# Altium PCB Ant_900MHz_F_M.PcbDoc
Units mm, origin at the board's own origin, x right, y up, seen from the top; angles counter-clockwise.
Board outline 23.3 x 33.3 mm, 2 copper layers (Top Layer, Bottom Layer), stack 1.633 mm thick; 3 components, 3 nets, 5 pads, 38 vias.
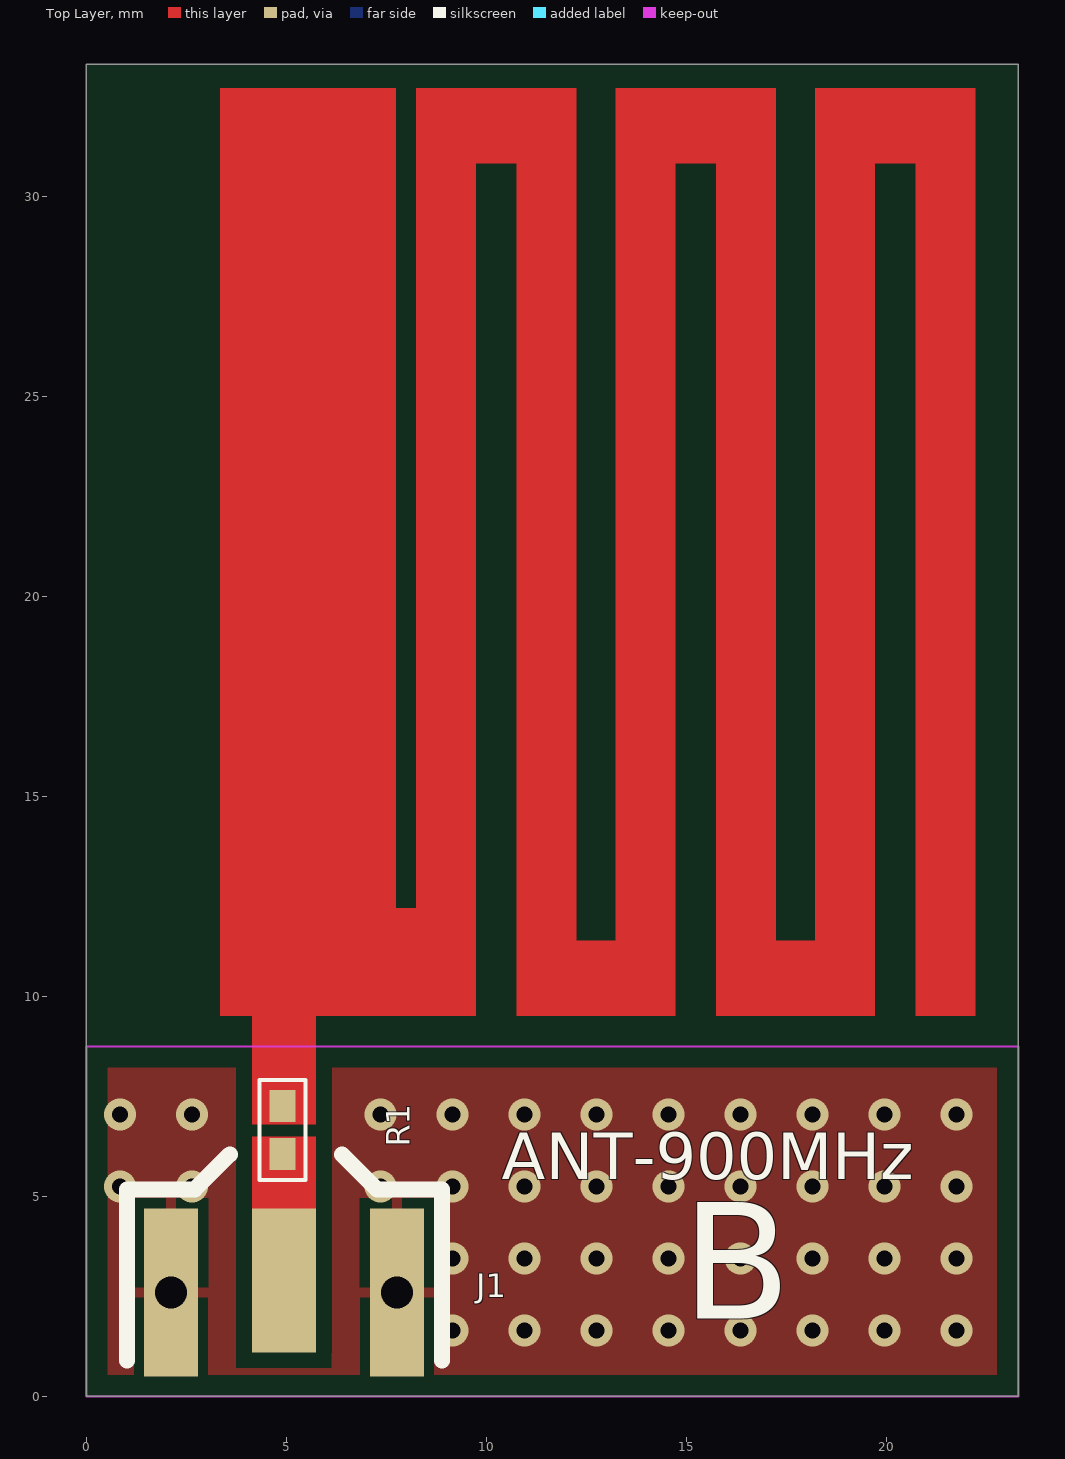
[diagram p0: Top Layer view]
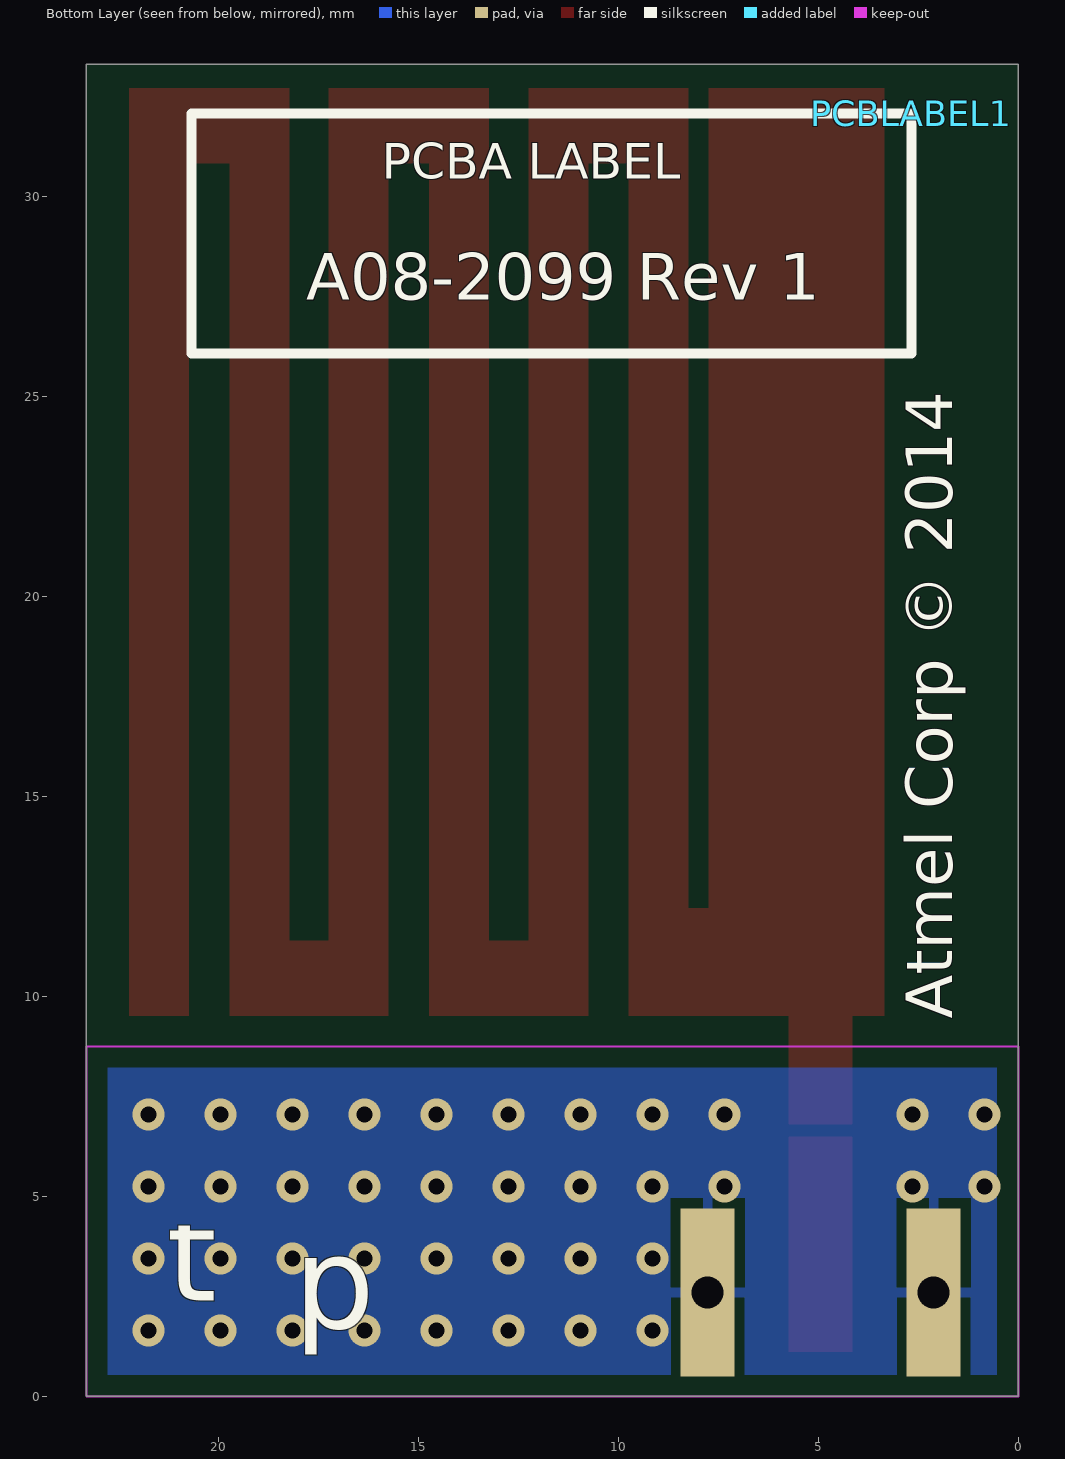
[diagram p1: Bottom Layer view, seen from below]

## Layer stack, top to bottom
Top Solder: solder mask 0.0102, Solder Resist, Dk 3.5
Top Layer: signal copper 0.0356
Dielectric1: core 1.562, FR-4, Dk 4.8
Bottom Layer: signal copper 0.0356
Bottom Solder: solder mask 0.0102, Solder Resist, Dk 3.5

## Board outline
0,0 0,33.3 23.3,33.3 23.3,0

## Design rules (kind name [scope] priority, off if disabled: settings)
AssemblyTestPointUsage [All] p1 off:
AssemblyTestpoint [All] p1 off: testpointundercomponent=TRUE minsize=1.016 maxsize=2.54 preferedsize=1.524 minholesize=0 maxholesize=1.016 preferedholesize=0.813 testpointgrid=0.025 usegrid=TRUE gridtolerance=0 allowsidetop=TRUE allowsidebottom=TRUE
Clearance Clearance_keepout [OnLayer('Keep-Out Layer')] p1: gap=0.5
Clearance Clearance_stripline [All vs (InNet('ANT') or InNet('NetJ1_1'))] p2: gap=0.4
ComponentClearance [All] p1 off: gap=0.254 collisioncheckmode=3 verticalgap=0.254 showdistances=FALSE
DiffPairsRouting [All] p1 off: maxlimit=0.254 minlimit=0.254 mostfreqgap=0.254 toplayer_minwidth=0.381 toplayer_maxwidth=0.381 toplayer_prefwidth=0.381 bottomlayer_minwidth=0.381 bottomlayer_maxwidth=0.381 bottomlayer_prefwidth=0.381 maxuncoupledlength=12.7
FabricationTestPointUsage [All] p1 off: valid=0 allowmultiple=FALSE
FabricationTestpoint [All] p1 off: side=3 testpointundercomponent=TRUE minsize=1.016 maxsize=2.54 preferedsize=1.524 minholesize=0 maxholesize=1.016 preferedholesize=0.813 testpointgrid=0.025 allowsidetop=TRUE allowsidebottom=TRUE usegrid=TRUE gridtolerance=0
FanoutControl Fanout_BGA [IsBGA] p1 off: bgadir=Out bgaviamode=Centered fanoutstyle=Auto fanoutdirection=Alternating viagrid=0.025 // Fanout_BGA (Default Rule)
FanoutControl Fanout_LCC [IsLCC] p2 off: bgadir=Out bgaviamode=Centered fanoutstyle=Auto fanoutdirection=Alternating viagrid=0.025 // Fanout_LCC (Default Rule)
FanoutControl Fanout_SOIC [IsSOIC] p3 off: bgadir=Out bgaviamode=Centered fanoutstyle=Auto fanoutdirection=Alternating viagrid=0.025 // Fanout_SOIC (Default Rule)
FanoutControl Fanout_Small [(CompPinCount < 5)] p4 off: bgadir=Out bgaviamode=Centered fanoutstyle=Auto fanoutdirection=OutThenIn viagrid=0.025 // Fanout_Small (Default Rule)
FanoutControl Fanout_Default [All] p5 off: bgadir=Out bgaviamode=Centered fanoutstyle=Auto fanoutdirection=Alternating viagrid=0.025 // Fanout_Default (Default Rule)
PlaneClearance [All] p1 off: clearance=0.4
PlaneConnect PlaneConnect_via [IsVia] p1 off: planeconnectstyle=Direct reliefexpansion=0.508 reliefentries=4 reliefconductorwidth=0.254 reliefairgap=0.254
PlaneConnect [All] p2 off: planeconnectstyle=Relief reliefexpansion=0.508 reliefentries=4 reliefconductorwidth=0.254 reliefairgap=0.254
PolygonConnect PolygonConnect_via [IsVia] p1: connectstyle=Direct reliefconductorwidth=0.254 reliefentries=4 polygonreliefangle="90 Angle" airgapwidth=0.254
PolygonConnect [All] p2: connectstyle=Relief reliefconductorwidth=0.254 reliefentries=4 polygonreliefangle="90 Angle" airgapwidth=0.254
RoutingVias [All] p1: holewidth=0.4 width=0.8 viastyle="Through Hole" minholewidth=0.3 minwidth=0.6 maxholewidth=0.5 maxwidth=1
SilkToSolderMaskClearance SilkscreenOverComponentPads [IsPad] p1: minsilkscreentomaskgap=0.2 clearancetoexposedcopper=TRUE
SolderMaskExpansion [All] p1: expansion=0.102
Width [All] p1: maxlimit=0.254 minlimit=0.254 preferedwidth=0.254
15 further rules are at their usual default settings.

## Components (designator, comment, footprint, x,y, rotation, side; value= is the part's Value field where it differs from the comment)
J1 "SMA connetor" AP8-00443 4.94,2.9 r90 top locked
PCBLABEL1 "PCBA_LABEL" AP8-00317 2.67,32.07 r0 bottom
R1 "Comment" AP2-00000 4.9,6.66 r90 top

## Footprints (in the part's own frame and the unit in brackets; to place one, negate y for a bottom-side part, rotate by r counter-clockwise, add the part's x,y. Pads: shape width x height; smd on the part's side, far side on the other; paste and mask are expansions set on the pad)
AP2-00000 [mm] "Standard 0402 SMD resistor footprint"
  rect 0.8x0.65 smd: 1(-0.6,0) 2(0.6,0)
  silkscreen extent -1.25,-0.58 1.25,0.58, body extent -0.5,-0.3 0.5,0.3, height 0.2
AP8-00317 [mm] "Placement area for 18x6mm sticker"
  silkscreen extent 0,0 18,6
AP8-00443 [mm] "SMA card edge mount 1.6mm substrate"
  rect 3.6x1.6 smd mask+0: 1(0,0)
  rect 4.2x1.35 hole 0.8 paste-0.3 mask+0: 2(-0.3,-2.825) 2.1(-0.3,2.825)
  silkscreen extent -2,-3.95 3.15,3.92, body extent -12.17,-3.18 1.16,3.18, height 3.71

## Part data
J1: library part A08-1047, "End Launch Jack Receptacle, Round Contact (de21535)"
PCBLABEL1: library part A09-0611, "PCBA identification label PP Top White Gloss"
R1: library part A02-0163, "RES 0.0 OHM 1/16W 0402 SMD"

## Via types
v1: diameter 0.8, hole 0.4, Top Layer to Bottom Layer, tented both sides, 38 vias

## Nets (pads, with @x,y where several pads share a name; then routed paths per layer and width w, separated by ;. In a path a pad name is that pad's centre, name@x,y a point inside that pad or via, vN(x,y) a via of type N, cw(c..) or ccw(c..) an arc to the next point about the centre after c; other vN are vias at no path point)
ANT: R1.2
gnd: J1.2 J1.2.1
  other v1: 9.15,1.65 10.95,1.65 12.75,1.65 14.55,1.65 16.35,1.65 18.15,1.65 19.95,1.65 21.75,1.65 9.15,3.45 10.95,3.45 12.75,3.45 14.55,3.45 16.35,3.45 18.15,3.45 19.95,3.45 21.75,3.45 0.84,5.25 2.64,5.25 7.35,5.25 9.15,5.25 10.95,5.25 12.75,5.25 14.55,5.25 16.35,5.25 18.15,5.25 19.95,5.25 21.75,5.25 0.84,7.05 2.64,7.05 7.35,7.05 9.15,7.05 10.95,7.05 12.75,7.05 14.55,7.05 16.35,7.05 18.15,7.05 19.95,7.05 21.75,7.05
NetJ1_1: J1.1 R1.1

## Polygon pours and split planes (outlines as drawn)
gnd on Bottom Layer "GND-No Net" (solid, pour order 7): 0,8.745 0,0 23.3,0 23.3,8.745 0,8.745
gnd on Top Layer "GND-No Net" (solid, remove dead copper, pour order 5): 0,9.2 0,0 23.3,0 23.3,9.2 0,9.2

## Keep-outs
Keep-Out Layer:
  lines w0.05: 0,0 23.3,0 23.3,8.745 0,8.745 0,0

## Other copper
Top Layer:
  rectangle net ANT: 18.219,9.51 19.719,32.71
  rectangle net ANT: 19.719,30.82 20.729,32.71
  rectangle net ANT: 20.729,9.51 22.229,32.71
  rectangle net ANT: 17.24,9.51 18.25,11.4
  rectangle net NetJ1_1: 4.14,1.105 5.74,6.49
  rectangle net ANT: 3.34,9.51 7.74,32.71
  rectangle net ANT: 8.24,9.51 9.74,32.71
  rectangle net ANT: 7.74,9.51 8.271,12.21
  rectangle net ANT: 4.14,6.8 5.74,9.51
  rectangle net ANT: 9.74,30.82 10.75,32.71
  rectangle net ANT: 10.75,9.51 12.25,32.71
  rectangle net ANT: 12.25,9.51 13.26,11.4
  rectangle net ANT: 15.74,9.51 17.24,32.71
  rectangle net ANT: 14.73,30.82 15.74,32.71
  rectangle net ANT: 13.23,9.51 14.73,32.71
  pour cut-out: 3.732,6.8 3.732,6.49 6.148,6.49 6.148,6.8

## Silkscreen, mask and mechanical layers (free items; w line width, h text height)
Top Overlay:
  text "ANT-900MHz" at 10.39,5.04 h2
  text "B" at 14.89,0.97 h5
Bottom Overlay:
  text "A08-2099 Rev 1" at 17.8,27.02 h2
  text "Atmel Corp © 2014" at 1.26,9.44 h2 r270
  text "t" at 21.283,1.641 h4
  text "p" at 18.11,0.94 h4
Top Paste:
  rectangle: 7.19,0.8 8.29,4.5
  rectangle: 1.54,0.8 2.64,4.5
Bottom Paste:
  rectangle: 1.54,0.8 2.64,4.5
  rectangle: 7.19,0.8 8.29,4.5
Top Solder:
  rectangle: 3.07,5.13 3.732,8.22
  rectangle: 6.148,5.11 6.82,8.2
  rectangle: 4.14,7.9 5.74,9.6
  rectangle: 4.14,5 5.74,5.4
Mechanical 1:
  the board outline again, w0.2
Mechanical 4:
  drawing of 171 lines, arcs and shapes, not listed
  text "Layer stackup" at -105.45,85.43 h5
  text "SOLDER LEVEL" at -85.86,74.402 h1.78
  text "( SEE NOTE 2A )" at -62.873,74.402 h1.78
  text "COPPER PLATE" at -85.86,71.862 h1.78
  text "35 um" at -60.587,70.592 h1.78
  text "LAYER 1" at -119.134,69.322 h1.78
  text "COPPER FOIL" at -85.86,69.322 h1.78
  text "}" at -64.143,69.195 h4.44
  text "( SEE NOTE 1A )" at -53.49,48.93 h1.78
  text "CORE" at -85.16,48.891 h1.78
  text "1526 um" at -70.809,48.891 h1.78
  text "Note 3" at -133.23,48.84 h1.52
  text "Prepregs" at -85.646,31.548 h1.78
  text "LAYER 2" at -116.43,27.81 h1.78
  text "COPPER FOIL" at -85.86,27.412 h1.78
  text "35 um" at -60.587,26.142 h1.78
  text "COPPER PLATE" at -85.86,24.872 h1.78
  text "}" at -64.143,24.745 h4.44
  text "SOLDER LEVEL" at -85.86,22.332 h1.78
  text "( SEE NOTE 2A )" at -62.873,22.332 h1.78
  text "NOTE  1A:  FR4" at -112.862,14.791 h1.78
  text "2A:  SURFACE PROTECTION: Chemical Gold" at -103.959,11.089 h1.78
  text "3:  PCB Thickness to be calculated based on Stack up" at -102.505,8.035 h1.52
  text "THE BOARD MUST BE RoHS COMPLIANT" at -104.104,5.127 h1.78
  text "DETAIL A ( CROSS-SECTION )" at -112.365,-0.119 h3.05
  text "SCALE = NONE" at -93.188,-4.691 h1.78
Mechanical 16:
  lines w0.127: -203.991,-61.722 -198.911,-61.722 ; -203.991,8.938 -198.911,8.938 ; -203.991,79.423 -198.911,79.423 ; -154.715,-132.207 -154.715,-127.127 ; -154.715,144.653 -154.715,149.733 ; -110.691,144.653 -110.691,149.733 ; -105.566,-132.207 -105.566,-127.127 ; -61.516,144.653 -61.516,149.733 ; -56.417,-132.207 -56.417,-127.127 ; -7.141,-132.207 -7.141,-127.127 ; -7.141,144.653 -7.141,149.733 ; 42.008,-132.207 42.008,-127.127 ; 42.008,144.653 42.008,149.733 ; 70.329,-119.507 184.629,-119.507 ; 70.329,-111.887 184.629,-111.887 ; 70.329,-104.267 108.429,-104.267 ; 91.157,-132.207 91.157,-127.127 ; 91.157,144.653 91.157,149.733 ; 108.429,-127.127 108.429,-111.887 108.429,-96.647 ; 140.433,-132.207 140.433,-127.127 ; 140.433,144.653 140.433,149.733 ; 161.769,-127.127 161.769,-111.887 ; 184.629,-61.722 189.709,-61.722 ; 184.629,8.893 189.709,8.893 ; 184.629,79.378 189.709,79.378 ; 70.329,-127.127 70.329,-96.647 ; 70.329,-127.127 184.629,-127.127 ; 70.329,-127.127 34.769,-127.127 34.769,-96.647 70.329,-96.647 ; 70.329,-96.647 108.429,-96.647 ; 108.429,-96.647 184.629,-96.647 184.629,-127.127 ; 184.629,-127.127 184.629,144.653 -198.911,144.653 -198.911,-127.127 184.629,-127.127 ; -203.991,-132.207 189.709,-132.207 189.709,149.733 -203.991,149.733 -203.991,-132.207
  text "1" at -179.954,146.304 h0.67
  text "4" at -32.363,146.304 h0.67
  text "5" at 16.913,146.304 h0.67
  text "6" at 65.935,146.304 h0.67
  text "7" at 115.465,146.304 h0.67
  text "8" at 164.487,146.304 h0.67
  text "2" at -133.465,146.168 h0.67
  text "3" at -86.915,146.018 h0.67
  text "A" at -202.086,112.494 h0.67
  text "A" at 186.534,112.449 h0.67
  text "B" at 186.614,44.394 h0.67
  text "B" at -202.086,41.882 h0.67
  text "C" at -202.179,-26.295 h0.67
  text "C" at 186.984,-31.907 h0.67
  text "D" at -202.086,-99.009 h0.67
  text "D" at 186.534,-99.009 h0.67
  text "ENGINEER:" at 71.599,-99.187 h0.67
  text "TITLE:" at 109.699,-99.187 h0.67
  text "PCB DESIGNER:" at 71.599,-106.68 h0.67
  text "B" at 35.759,-111.807 h22
  text "DATE:" at 71.599,-114.427 h0.67
  text "PART NO.:" at 109.699,-114.427 h0.67
  text "REV:" at 163.039,-114.427 h0.67
  text ".PRINT_DATE" at 71.709,-118.307 h0.67
  text "ATMEL NORWAY" at 39.009,-119.207 h0.67
  text "Vestre Rosten 79" at 38.979,-121.285 h0.67
  text "FILE NAME:" at 71.599,-122.047 h0.67
  text "DWG NO:" at 109.699,-122.047 h0.67
  text "SCALE:" at 163.039,-122.047 h0.67
  text "N-7075 Tiller" at 38.979,-124.587 h0.67
  text ".PCB_FILE_NAME_NO_PATH" at 72.869,-125.095 h0.67
  text "2" at -130.331,-130.495 h0.67
  text "3" at -80.801,-130.495 h0.67
  text "4" at -31.779,-130.495 h0.67
  text "5" at 16.913,-130.495 h0.67
  text "6" at 65.935,-130.495 h0.67
  text "7" at 115.465,-130.495 h0.67
  text "8" at 164.487,-130.495 h0.67

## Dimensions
23.3,33.3 to 23.3,0 on Mechanical 4
0,33.3 to 23.3,33.3 on Mechanical 4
